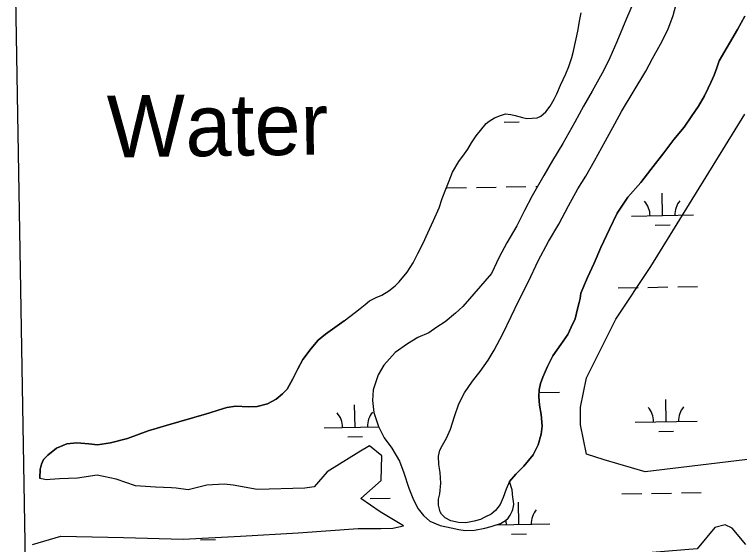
# Model space of a CAD drawing. Extents: x 3903937 to 3942190, y 260677 to 286651.
# Drawn here: x 3908015 to 3909185, y 276026 to 276881 of the extents above; entities that cross this region are included whole.
import ezdxf

# ---------------------------------------------------------------- set-up
doc = ezdxf.new("R2010")
doc.units = 0
for name, color, linetype in [('V-GRID-FRAM', 7, 'Continuous'), ('V-RIVR-IDEN', 7, 'Continuous'), ('V-SITE-VEGE', 7, 'Continuous'), ('V-TOPO-SHOR', 7, 'Continuous'), ('V-WETL-SWMP', 7, 'Continuous')]:
    doc.layers.add(name, color=color, linetype=linetype)

msp = doc.modelspace()

# ---------------------------------------------------------------- linework, layer by layer
at = {"layer": 'V-GRID-FRAM'}
msp.add_lwpolyline([(3907892.2, 284196.1), (3939773.2, 284757.2), (3940101.1, 266577.6), (3908204.3, 266016.2), (3907892.2, 284196.1)], dxfattribs=at)
at = {"layer": 'V-SITE-VEGE'}
msp.add_lwpolyline([(3909269, 276171.7), (3909032.6, 276143.3), (3908966.4, 276162.2), (3908938, 276171.7), (3908928.5, 276219), (3908928.5, 276247.3), (3908938, 276294.7), (3908985.3, 276389.3), (3909042, 276474.4), (3909193.3, 276720.5)], dxfattribs=at)
at = {"layer": 'V-TOPO-SHOR'}
for points in [[(3908813.5, 276127.4), (3908808.1, 276115.1), (3908803.5, 276101.6), (3908798.5, 276090.1), (3908791.1, 276080.9), (3908784, 276074.6), (3908774.2, 276069.7), (3908766.7, 276066.1), (3908756.5, 276063.2), (3908743.1, 276060.7), (3908731.2, 276061.4), (3908719.3, 276063.7), (3908710.2, 276068.7), (3908703.8, 276074.6), (3908701.8, 276078.5), (3908699.3, 276089.5), (3908699.2, 276099), (3908701.1, 276107.3), (3908702.9, 276124.7), (3908702, 276142.1), (3908699.9, 276155.1), (3908699.4, 276168.1), (3908701.6, 276178), (3908705.5, 276185.9), (3908712.1, 276197.5), (3908718.3, 276212.1), (3908724.8, 276232.3), (3908732.1, 276252.6), (3908741, 276270.8), (3908754.3, 276289.5), (3908766.3, 276305), (3908779.2, 276323.3), (3908788.9, 276339.6), (3908802.9, 276365.8), (3908816.4, 276394), (3908828.8, 276419.4), (3908844.3, 276450.3), (3908860.2, 276483.7), (3908876.8, 276515), (3908893.6, 276542.8), (3908908.7, 276572.6), (3908924.2, 276599.6), (3908937, 276620.3), (3908951, 276644.9), (3908968.5, 276677.4), (3908983.6, 276704.8), (3908994.5, 276724.7), (3909033.7, 276789.8), (3909044.6, 276810.1), (3909057.4, 276833.1), (3909069, 276856.5), (3909077.9, 276879.5), (3909083.6, 276901.7)], [(3908546.8, 276387), (3908565.1, 276400.6), (3908573, 276406.6), (3908580.8, 276413.4), (3908587.8, 276419.3), (3908598.8, 276424.6), (3908607.8, 276428.2), (3908619.1, 276435), (3908629.3, 276443), (3908635.9, 276449.7), (3908648.4, 276465.2), (3908658.1, 276480.3), (3908665.8, 276495.7), (3908674.7, 276512.3), (3908682, 276528.9), (3908691.3, 276548.7), (3908700.1, 276568.9), (3908705.1, 276584.3), (3908711.2, 276599.3), (3908716.6, 276612.7), (3908721.6, 276626.6), (3908732.1, 276644), (3908741.4, 276656.3), (3908746.4, 276663.8), (3908752.6, 276674.1), (3908760, 276685.6), (3908776, 276705.1), (3908781, 276709), (3908789.7, 276714.2), (3908799.1, 276718.3), (3908807.3, 276720.7), (3908816, 276720), (3908822.7, 276718.1), (3908828.6, 276716.6), (3908834.5, 276714.7), (3908841.6, 276713.6), (3908850.3, 276713.7), (3908858.6, 276714.5), (3908864.4, 276717.3), (3908872.6, 276724.1), (3908879.6, 276733.2), (3908885.8, 276744.3), (3908890.1, 276753.4), (3908896.2, 276766.9), (3908904.7, 276785.5), (3908909.3, 276797.3), (3908914.3, 276811.9), (3908917, 276821.8), (3908919.2, 276832.4), (3908922.2, 276847), (3908924.5, 276856.9), (3908926.7, 276870.7), (3908929.3, 276884.1)], [(3909193.6, 276878.3), (3909181.5, 276857.2), (3909152, 276806.4), (3909148.2, 276794.9), (3909144, 276783.4), (3909138.5, 276771.5), (3909134.3, 276762.4), (3909128.1, 276749.7), (3909118.8, 276733), (3909107.9, 276717.5), (3909095.4, 276699.2), (3909079, 276679.3), (3909063, 276657.8), (3909042, 276630.8)], [(3909042, 276630.8), (3909025.6, 276610.1), (3909004.9, 276586.6), (3908987.4, 276560.7), (3908975, 276534.9), (3908961.1, 276505.2), (3908950.3, 276479.8), (3908939.4, 276456.8), (3908928.6, 276431.4), (3908927.5, 276422.7), (3908926, 276416.4), (3908924.1, 276408.1), (3908919.5, 276389.9), (3908913.4, 276376.4), (3908907.9, 276364.9), (3908896.6, 276348.6), (3908883.8, 276330.3), (3908875.3, 276312.8), (3908867.5, 276295.7), (3908863.7, 276285.8), (3908861.8, 276275.2), (3908861.1, 276264.5), (3908862.1, 276250.7), (3908865, 276235.7), (3908866.3, 276216.7), (3908864.9, 276204.1), (3908859.9, 276186.7), (3908851.8, 276170.4), (3908837, 276152.1), (3908823.7, 276139.3), (3908813.5, 276127.4)], [(3908546.8, 276387), (3908516.8, 276365.3), (3908504.8, 276355.4), (3908493.6, 276342.1), (3908480.5, 276324.4), (3908472, 276309.3), (3908464.4, 276293.3), (3908455, 276276.4), (3908447.6, 276268.8), (3908437.1, 276260.6), (3908423.1, 276252.8), (3908406.8, 276248.5), (3908392, 276248.2), (3908372.2, 276249.3), (3908357.7, 276246.7), (3908343.8, 276242.6), (3908330.1, 276238.1), (3908324.7, 276236.7), (3908259.6, 276218), (3908230.8, 276209.4), (3908197.7, 276196.7), (3908170.2, 276189.9), (3908149.1, 276186.8), (3908135, 276188.4), (3908115.5, 276189.8), (3908099.5, 276188.1), (3908082.8, 276181.3), (3908069, 276169.9), (3908061.9, 276162.9), (3908058.7, 276155.2), (3908057, 276149.2), (3908056.7, 276147.7), (3908056, 276132.1)], [(3908044.3, 276025.8), (3908090.1, 276039.4), (3908190.9, 276036.8), (3908287.2, 276034.5), (3908379.7, 276039), (3908472.8, 276044.7), (3908569.7, 276051.8), (3908606.3, 276051.5), (3908625.7, 276052.1), (3908642.5, 276055.7), (3908605.1, 276078.7), (3908573.9, 276099.9), (3908606.6, 276129.3), (3908607.6, 276169.1), (3908587.9, 276184.8), (3908570.5, 276174.7), (3908519.8, 276142.9), (3908498.5, 276118.8), (3908483.3, 276116.7), (3908406.7, 276114.5), (3908367.9, 276121.6), (3908353.2, 276123.3), (3908325.2, 276121.5), (3908295.5, 276114), (3908276, 276116.7), (3908268.2, 276117), (3908242.6, 276118.1), (3908210.5, 276120.5), (3908178.9, 276131), (3908148.6, 276137.6), (3908116.8, 276132.8), (3908087.7, 276131.8), (3908072.6, 276130.5), (3908066.5, 276130), (3908056, 276132.1)], [(3909195, 276025.9), (3909172.8, 276052.2), (3909161.8, 276057.3), (3909144.9, 276053), (3909116.5, 276018.8), (3909043.7, 276012.6), (3908922.5, 276009.1), (3908779.6, 275998.6), (3908721.3, 275999.9), (3908666.3, 275997.1), (3908615, 275988.2), (3908497.8, 275968.3), (3908449.6, 275959.3), (3908386.5, 275957.4), (3908341.4, 275963.1), (3908308.2, 275961.6), (3908270.8, 275958), (3908199.8, 275934.3), (3908130.8, 275935.4), (3908034.2, 275926.6)]]:
    msp.add_lwpolyline(points, dxfattribs=at)
at = {"layer": 'V-WETL-SWMP'}
for p, q in [((3909014.8, 276903.4), (3909002.5, 276874.9)), ((3908926.7, 276870.7), (3908929.3, 276884.1)), ((3909181.5, 276857.2), (3909193.6, 276878.3)), ((3908924.5, 276856.9), (3908926.7, 276870.7)), ((3909002.5, 276874.9), (3908986.7, 276837.3)), ((3908922.2, 276847), (3908924.5, 276856.9)), ((3909152, 276806.4), (3909181.5, 276857.2)), ((3908919.2, 276832.4), (3908922.2, 276847)), ((3908917, 276821.8), (3908919.2, 276832.4)), ((3908986.7, 276837.3), (3908975.5, 276811.5)), ((3908914.3, 276811.9), (3908917, 276821.8)), ((3908909.3, 276797.3), (3908914.3, 276811.9)), ((3908975.5, 276811.5), (3908966.2, 276791.3)), ((3908904.7, 276785.5), (3908909.3, 276797.3)), ((3909148.2, 276794.9), (3909152, 276806.4)), ((3908896.2, 276766.9), (3908904.7, 276785.5)), ((3908966.2, 276791.3), (3908947.2, 276757.6)), ((3909138.5, 276771.5), (3909144, 276783.4)), ((3909144, 276783.4), (3909148.2, 276794.9)), ((3908890.1, 276753.4), (3908896.2, 276766.9)), ((3909128.1, 276749.7), (3909134.3, 276762.4)), ((3909134.3, 276762.4), (3909138.5, 276771.5)), ((3908885.8, 276744.3), (3908890.1, 276753.4)), ((3908947.2, 276757.6), (3908933.3, 276733.4)), ((3909118.8, 276733), (3909128.1, 276749.7)), ((3908879.6, 276733.2), (3908885.8, 276744.3)), ((3908872.6, 276724.1), (3908879.6, 276733.2)), ((3908933.3, 276733.4), (3908919, 276707.3)), ((3909107.9, 276717.5), (3909118.8, 276733)), ((3908781, 276709), (3908789.7, 276714.2)), ((3908789.7, 276714.2), (3908799.1, 276718.3)), ((3908799.1, 276718.3), (3908807.3, 276720.7)), ((3908807.3, 276720.7), (3908816, 276720)), ((3908816, 276720), (3908822.7, 276718.1)), ((3908822.7, 276718.1), (3908828.6, 276716.6)), ((3908828.6, 276716.6), (3908834.5, 276714.7)), ((3908834.5, 276714.7), (3908841.6, 276713.6)), ((3908841.6, 276713.6), (3908850.3, 276713.7)), ((3908850.3, 276713.7), (3908858.6, 276714.5)), ((3908858.6, 276714.5), (3908864.4, 276717.3)), ((3908864.4, 276717.3), (3908872.6, 276724.1)), ((3909095.4, 276699.2), (3909107.9, 276717.5)), ((3908760, 276685.6), (3908776, 276705.1)), ((3908776, 276705.1), (3908781, 276709)), ((3908805.3, 276707.6), (3908829.3, 276708)), ((3908919, 276707.3), (3908900, 276673.2)), ((3909079, 276679.3), (3909095.4, 276699.2)), ((3908752.6, 276674.1), (3908760, 276685.6)), ((3909063, 276657.8), (3909079, 276679.3)), ((3908746.4, 276663.8), (3908752.6, 276674.1)), ((3908900, 276673.2), (3908883.3, 276645.4)), ((3908732.1, 276644), (3908741.4, 276656.3)), ((3908741.4, 276656.3), (3908746.4, 276663.8)), ((3909042, 276630.8), (3909063, 276657.8)), ((3908721.6, 276626.6), (3908732.1, 276644)), ((3908883.3, 276645.4), (3908868.9, 276621.2)), ((3908716.6, 276612.7), (3908721.6, 276626.6)), ((3908868.9, 276621.2), (3908850.3, 276588.7)), ((3909025.6, 276610.1), (3909042, 276630.8)), ((3908711.2, 276599.3), (3908716.6, 276612.7)), ((3909004.9, 276586.6), (3909025.6, 276610.1)), ((3908705.1, 276584.3), (3908711.2, 276599.3)), ((3908712.4, 276601.3), (3908744.3, 276601.9)), ((3908760.3, 276602.1), (3908792.3, 276602.7)), ((3908808.3, 276603), (3908840.3, 276603.5)), ((3908856.3, 276603.8), (3908859, 276603.9)), ((3908850.3, 276588.7), (3908838, 276564.6)), ((3908987.4, 276560.7), (3909004.9, 276586.6)), ((3909060.5, 276556.7), (3909059.9, 276592.7)), ((3908700.1, 276568.9), (3908705.1, 276584.3)), ((3908691.3, 276548.7), (3908700.1, 276568.9)), ((3908838, 276564.6), (3908825.6, 276540)), ((3908975, 276534.9), (3908987.4, 276560.7)), ((3909010.5, 276555.8), (3909110.5, 276557.6)), ((3908682, 276528.9), (3908691.3, 276548.7)), ((3908825.6, 276540), (3908809.7, 276512.6)), ((3909048.8, 276541), (3909072.8, 276541.5)), ((3908674.7, 276512.3), (3908682, 276528.9)), ((3908961.1, 276505.2), (3908975, 276534.9)), ((3908665.8, 276495.7), (3908674.7, 276512.3)), ((3908809.7, 276512.6), (3908797.3, 276489.7)), ((3908950.3, 276479.8), (3908961.1, 276505.2)), ((3908658.1, 276480.3), (3908665.8, 276495.7)), ((3908648.4, 276465.2), (3908658.1, 276480.3)), ((3908797.3, 276489.7), (3908784.6, 276463.1)), ((3908939.4, 276456.8), (3908950.3, 276479.8)), ((3908635.9, 276449.7), (3908648.4, 276465.2)), ((3908784.6, 276463.1), (3908738.6, 276409.8)), ((3908928.6, 276431.4), (3908939.4, 276456.8)), ((3908629.3, 276443), (3908635.9, 276449.7)), ((3908607.8, 276428.2), (3908619.1, 276435)), ((3908619.1, 276435), (3908629.3, 276443)), ((3908989.1, 276440), (3909021.1, 276440.5)), ((3909037.1, 276440.8), (3909069.1, 276441.4)), ((3909085.1, 276441.7), (3909117.1, 276442.2)), ((3908587.8, 276419.3), (3908598.8, 276424.6)), ((3908598.8, 276424.6), (3908607.8, 276428.2)), ((3908926, 276416.4), (3908927.5, 276422.7)), ((3908927.5, 276422.7), (3908928.6, 276431.4)), ((3908573, 276406.6), (3908580.8, 276413.4)), ((3908580.8, 276413.4), (3908587.8, 276419.3)), ((3908738.6, 276409.8), (3908726.8, 276399.1)), ((3908924.1, 276408.1), (3908926, 276416.4)), ((3908546.8, 276387), (3908565.1, 276400.6)), ((3908565.1, 276400.6), (3908573, 276406.6)), ((3908726.8, 276399.1), (3908710, 276385.1)), ((3908919.5, 276389.9), (3908924.1, 276408.1)), ((3908516.8, 276365.3), (3908546.8, 276387)), ((3908913.4, 276376.4), (3908919.5, 276389.9)), ((3908696.7, 276376.3), (3908683.4, 276367.5)), ((3908710, 276385.1), (3908696.7, 276376.3)), ((3908907.9, 276364.9), (3908913.4, 276376.4)), ((3908504.8, 276355.4), (3908516.8, 276365.3)), ((3908683.4, 276367.5), (3908666.1, 276359.9)), ((3908896.6, 276348.6), (3908907.9, 276364.9)), ((3908493.6, 276342.1), (3908504.8, 276355.4)), ((3908666.1, 276359.9), (3908649.3, 276349.8)), ((3908480.5, 276324.4), (3908493.6, 276342.1)), ((3908649.3, 276349.8), (3908629.3, 276335.8)), ((3908883.8, 276330.3), (3908896.6, 276348.6)), ((3908629.3, 276335.8), (3908611, 276315.2)), ((3908875.3, 276312.8), (3908883.8, 276330.3)), ((3908472, 276309.3), (3908480.5, 276324.4)), ((3908464.4, 276293.3), (3908472, 276309.3)), ((3908611, 276315.2), (3908602, 276299.7)), ((3908867.5, 276295.7), (3908875.3, 276312.8)), ((3908455, 276276.4), (3908464.4, 276293.3)), ((3908602, 276299.7), (3908593.6, 276275.6)), ((3908863.7, 276285.8), (3908867.5, 276295.7)), ((3908861.8, 276275.2), (3908863.7, 276285.8)), ((3908437.1, 276260.6), (3908447.6, 276268.7)), ((3908447.6, 276268.7), (3908455, 276276.4)), ((3908593.6, 276275.6), (3908592.6, 276258.2)), ((3908861.1, 276264.5), (3908861.8, 276275.2)), ((3908862.2, 276271.2), (3908894.2, 276271.8)), ((3908423.1, 276252.8), (3908437.1, 276260.6)), ((3908592.6, 276258.2), (3908595.1, 276238.9)), ((3908862.1, 276250.7), (3908861.1, 276264.5)), ((3909066.4, 276224), (3909065.7, 276260)), ((3908343.8, 276242.6), (3908357.7, 276246.7)), ((3908357.7, 276246.7), (3908372.2, 276249.3)), ((3908372.2, 276249.3), (3908392, 276248.2)), ((3908392, 276248.2), (3908406.8, 276248.5)), ((3908406.8, 276248.5), (3908423.1, 276252.8)), ((3908564.5, 276215.2), (3908563.9, 276251.2)), ((3908865, 276235.7), (3908862.1, 276250.7)), ((3908259.6, 276218), (3908324.7, 276236.7)), ((3908324.7, 276236.7), (3908330.1, 276238.1)), ((3908330.1, 276238.1), (3908343.8, 276242.6)), ((3908595.1, 276238.9), (3908602.5, 276216.1)), ((3908866.3, 276216.7), (3908865, 276235.7)), ((3909016.4, 276223.2), (3909116.4, 276224.9)), ((3908230.8, 276209.4), (3908259.6, 276218)), ((3908514.5, 276214.3), (3908602.6, 276215.9)), ((3908602.5, 276216.1), (3908611.7, 276197.7)), ((3908864.9, 276204.1), (3908866.3, 276216.7)), ((3908197.7, 276196.7), (3908230.8, 276209.4)), ((3908552.8, 276199.6), (3908576.8, 276200)), ((3908859.9, 276186.7), (3908864.9, 276204.1)), ((3909054.6, 276208.4), (3909078.6, 276208.8)), ((3908082.8, 276181.3), (3908099.5, 276188.1)), ((3908099.5, 276188.1), (3908115.5, 276189.8)), ((3908115.5, 276189.8), (3908135, 276188.4)), ((3908135, 276188.4), (3908149.1, 276186.8)), ((3908149.1, 276186.8), (3908170.2, 276189.9)), ((3908170.2, 276189.9), (3908197.7, 276196.7)), ((3908611.7, 276197.7), (3908624.1, 276181.2)), ((3908069, 276169.9), (3908082.8, 276181.3)), ((3908587.9, 276184.8), (3908570.5, 276174.7)), ((3908607.6, 276169.1), (3908587.9, 276184.8)), ((3908624.1, 276181.2), (3908636.5, 276160.5)), ((3908851.8, 276170.4), (3908859.9, 276186.7)), ((3908061.9, 276162.9), (3908069, 276169.9)), ((3908570.5, 276174.7), (3908519.8, 276142.9)), ((3908606.6, 276129.3), (3908607.6, 276169.1)), ((3908837, 276152.1), (3908851.8, 276170.4)), ((3908057, 276149.2), (3908058.7, 276155.2)), ((3908058.7, 276155.2), (3908061.9, 276162.9)), ((3908636.5, 276160.5), (3908643.4, 276141.2)), ((3908823.7, 276139.3), (3908837, 276152.1)), ((3908056, 276132.1), (3908056.7, 276147.7)), ((3908056.7, 276147.7), (3908057, 276149.2)), ((3908519.8, 276142.9), (3908498.5, 276118.8)), ((3908643.4, 276141.2), (3908651.1, 276116.9)), ((3908066.5, 276130), (3908056, 276132.1)), ((3908072.6, 276130.5), (3908066.5, 276130)), ((3908087.7, 276131.8), (3908072.6, 276130.5)), ((3908116.8, 276132.8), (3908087.7, 276131.8)), ((3908148.6, 276137.6), (3908116.8, 276132.8)), ((3908178.9, 276131), (3908148.6, 276137.6)), ((3908210.5, 276120.5), (3908178.9, 276131)), ((3908573.9, 276099.9), (3908606.6, 276129.3)), ((3908813.5, 276127.4), (3908823.7, 276139.3)), ((3908242.6, 276118.1), (3908210.5, 276120.5)), ((3908268.2, 276117), (3908242.6, 276118.1)), ((3908276, 276116.6), (3908268.2, 276117)), ((3908295.5, 276114), (3908276, 276116.6)), ((3908325.2, 276121.5), (3908295.5, 276114)), ((3908353.2, 276123.3), (3908325.2, 276121.5)), ((3908367.9, 276121.6), (3908353.2, 276123.3)), ((3908406.7, 276114.5), (3908367.9, 276121.6)), ((3908483.3, 276116.7), (3908406.7, 276114.5)), ((3908498.5, 276118.8), (3908483.3, 276116.7)), ((3908651.1, 276116.9), (3908658.8, 276097.6)), ((3908817.9, 276114), (3908813.5, 276127.4)), ((3908819.2, 276101.8), (3908817.9, 276114)), ((3908995, 276107.3), (3909027, 276107.9)), ((3909043, 276108.2), (3909075, 276108.8)), ((3909091, 276109), (3909123, 276109.6)), ((3908605.1, 276078.7), (3908573.9, 276099.9)), ((3908589.1, 276100.2), (3908621.1, 276100.8)), ((3908658.8, 276097.6), (3908666.5, 276083.1)), ((3908820.4, 276095.9), (3908819.2, 276101.8)), ((3908820.5, 276090.4), (3908820.4, 276095.9)), ((3908828.8, 276058), (3908828.1, 276094)), ((3908666.5, 276083.1), (3908675.2, 276072.5)), ((3908818.3, 276079.4), (3908819, 276082.1)), ((3908819, 276082.1), (3908820.5, 276090.4)), ((3908642.5, 276055.7), (3908605.1, 276078.7)), ((3908675.2, 276072.5), (3908685.2, 276063.2)), ((3908811.7, 276068.3), (3908814.8, 276073)), ((3908814.8, 276073), (3908818.3, 276079.4)), ((3908685.2, 276063.2), (3908701.8, 276056.6)), ((3908784.2, 276055), (3908799.2, 276059.5)), ((3908791.9, 276057.3), (3908878.8, 276058.9)), ((3908799.2, 276059.5), (3908807.4, 276064.7)), ((3908807.4, 276064.7), (3908811.7, 276068.3)), ((3908472.8, 276044.7), (3908569.7, 276051.8)), ((3908569.7, 276051.8), (3908606.3, 276051.5)), ((3908606.3, 276051.5), (3908625.7, 276052.1)), ((3908625.7, 276052.1), (3908642.5, 276055.7)), ((3908701.8, 276056.6), (3908719.6, 276052.9)), ((3908719.6, 276052.9), (3908732.2, 276049.8)), ((3908732.2, 276049.8), (3908742.1, 276048.4)), ((3908742.1, 276048.4), (3908757.5, 276048.9)), ((3908757.5, 276048.9), (3908774, 276052.2)), ((3908774, 276052.2), (3908784.2, 276055)), ((3909144.9, 276053), (3909116.5, 276018.8)), ((3909161.8, 276057.3), (3909144.9, 276053)), ((3909172.8, 276052.2), (3909161.8, 276057.3)), ((3909195, 276025.9), (3909172.8, 276052.2)), ((3908044.3, 276025.8), (3908090.1, 276039.4)), ((3908090.1, 276039.4), (3908190.9, 276036.8)), ((3908190.9, 276036.8), (3908287.2, 276034.5)), ((3908287.2, 276034.5), (3908379.7, 276039)), ((3908379.7, 276039), (3908472.8, 276044.7)), ((3908817, 276042.3), (3908841, 276042.8)), ((3908315.2, 276033.5), (3908339.2, 276033.9))]:
    msp.add_line(p, q, dxfattribs=at)
for centre, start, end in [((3909005.3, 276556.2), 0.2366, 41.7802), ((3909115.7, 276558.1), 140.2366, 181.7802), ((3909011.1, 276223.6), 0.2366, 41.7802), ((3909121.6, 276225.5), 140.2366, 181.7802), ((3908509.3, 276214.7), 0.2366, 41.7802), ((3908619.8, 276216.7), 140.2366, 181.7802), ((3908884, 276059.4), 140.2366, 181.7802), ((3908773.5, 276057.5), 0.2366, 12.5956)]:
    msp.add_arc(centre, 35.2, start, end, dxfattribs=at)

# ---------------------------------------------------------------- texts
at = {"layer": 'V-RIVR-IDEN'}
msp.add_text('Water', height=100, rotation=0.8184, dxfattribs=at).set_placement((3908165.2, 276650.3))

doc.saveas('drawing.dxf')
